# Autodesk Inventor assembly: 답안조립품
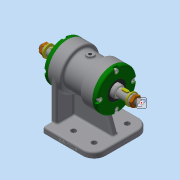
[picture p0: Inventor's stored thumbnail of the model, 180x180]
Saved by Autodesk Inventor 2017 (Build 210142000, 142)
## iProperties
Part Number: 답안조립품
Material: 일반
Document SubType Name: Assembly
Designer: mrc
Author: mrc
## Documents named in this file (12)
- C:\Users\mrc\Desktop\700606V1022\답안조립품.iam
- C:\Users\mrc\Desktop\700606V1022\본체.ipt
- C:\Users\mrc\Desktop\700606V1022\V-벨트풀리.ipt
- C:\Users\mrc\Desktop\700606V1022\너트 M10.ipt
- C:\Users\mrc\Desktop\700606V1022\베어링 6204.ipt
- C:\Users\mrc\Desktop\700606V1022\볼트 M4.ipt
- C:\Users\mrc\Desktop\700606V1022\스프링 와셔 10.ipt
- C:\Users\mrc\Desktop\700606V1022\오일 실 20 32 5.ipt
- C:\Users\mrc\Desktop\700606V1022\축.ipt
- C:\Users\mrc\Desktop\700606V1022\커버.ipt
- C:\Users\mrc\Desktop\700606V1022\키 5x5x12.ipt
- C:\Users\mrc\Desktop\700606V1022\평면 와셔 10x21.ipt
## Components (2 placed, 1 different names)
1. V-벨트풀리:1
2. V-벨트풀리:2
